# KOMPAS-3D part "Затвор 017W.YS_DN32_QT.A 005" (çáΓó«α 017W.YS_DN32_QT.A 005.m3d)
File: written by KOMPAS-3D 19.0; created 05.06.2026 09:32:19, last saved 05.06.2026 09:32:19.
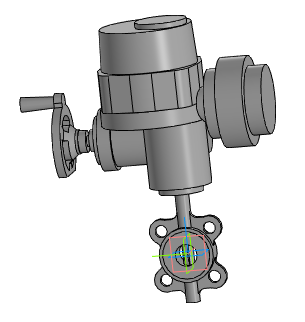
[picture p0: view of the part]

Document properties: Автор: Энергия; Полное имя файла: ..\..\..\3d для проектировщиков\x.x Тип 017W.Y(S) Затвор дисковый поворотный межфланцевый\Затвор 017W.Y(S)_DN32-DN1200_QT.A_MT903.A\Затвор 017W.YS_DN32_QT.A 005.a3d

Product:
- Part/product: Затвор 017W.YS_DN32_QT.A 005
    Масса: 37.5728

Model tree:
1. Операция без истории:1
